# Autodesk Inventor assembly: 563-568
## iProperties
Author: Administrator
Shininess: 64.0
Angle Display Precision: 2
Document Length Units: 11272
Document Angle Units: 11286
Document Time Units: 11279
Document Mass Units: 11290
Document Length Units Precision: 3
Document Angle Units Precision: 2
Compacted: True
PropertySet Name: _Private Model Information
Created: 2002-03
Part Number: 563-568
Document SubType Name: Assembly
Designer: Administrator
Control State: 0
Master: False
Checked Out: False
PropertySet Name: Design Tracking Control
Density: 0.0
Volumn: 0.0
Area: 0.0
PropertySet Name: Model Information
